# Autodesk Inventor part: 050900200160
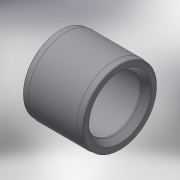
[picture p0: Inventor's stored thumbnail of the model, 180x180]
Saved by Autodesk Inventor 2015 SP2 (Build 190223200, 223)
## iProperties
Created: 2017-11
Part Number: 050900200160
Material: Generic
Description: PLASSON BUSHING-CEMENT PVC 200-160
Document SubType Name: Modeling
Designer: KIM
Density: 1 g/cm^3
Appearance: Default
Author: KIM
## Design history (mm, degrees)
derived "050900.ipt"
feature "Solid1::050900.ipt"
tag "TaggingFeature1"
body "Solid1"
other parameters: "d2" = 86, "d3" = 106, "d7" = 10.6, "d11" = 10.6, "d12" = 2, "d14" = 2, "d15" = 10.6, "d17" = 2, "d18" = 2, "d19" = 142.4, "d20" = 4, "d21" = 17.28, "L_" = 106, "l_" = 86, "z_" = 2
